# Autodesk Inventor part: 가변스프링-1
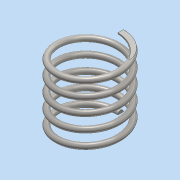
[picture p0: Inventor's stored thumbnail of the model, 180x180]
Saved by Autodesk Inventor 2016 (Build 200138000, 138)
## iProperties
Created: 2015-11
Part Number: 가변스프링-1
Material: 스테인레스 스틸
Document SubType Name: Modeling
Designer: Administrator
Density: 8 g/cm^3
Appearance: 반연마
Mass: 8.54233 g
Surface Area: 21.6566 cm^2
Volume: 1.06779 cm^3
Author: Administrator
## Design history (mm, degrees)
sketch "스케치2"
  geometry: L1 (0, 0)-(11, 0); L2 (11, 0)-(11, 25.508); L3 (11, 25.508)-(0, 25.508); L4 (0, 25.508)-(0, 0); C1 r 1 at (11, 0)
  constraints: 8 end point, 2 parallel, 1 centre point, 1 coincident, 1 horizontal, 1 perpendicular
  dimensions: "d0" = 2 diameter of C1; "d1" = 22 diameter of L2 L4; "d2" = 25.50829 distance between parallel lines of L3 L1 (derived)
feature "코일1" sketch "스케치2" pitch "d3" = 10; turns "d5" = 5; dims "d4" = 25.50829 (= d2), "d6" = 0, angle "d7" = 90 deg, angle "d8" = 90 deg, "d9" = 0, "d10" = 0
sketch "스케치3"
  geometry: L1 (0, 12)-(0, 10) reference; 1 further point
  constraints: 1 vertical alignment
extrude "돌출1" cut sketch "스케치3" distance "d11" = 10; taper "d12" = 0 deg
node "작업 평면1"
sketch "스케치4"
  geometry: L1 (0, -1)-(0, 1) reference; 1 further point
  constraints: 1 vertical alignment
extrude "돌출2" cut sketch "스케치4" distance "d13" = 10; taper "d14" = 0 deg
node "솔리드1"
node "절단 모서리 투영1"
node "절단 모서리 투영2"
